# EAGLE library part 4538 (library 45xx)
Dual precision monostable MULTIVIBRATOR
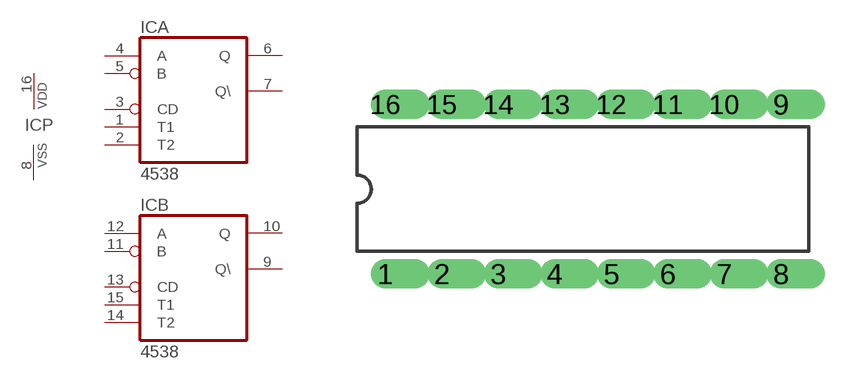
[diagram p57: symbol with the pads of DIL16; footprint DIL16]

Designator prefix IC; gates A=4528 B=4528 P=PWRN

## 4538N  [DIL16]
1  A:T1  in
2  A:T2  in
3  A:CD  in
4  A:A  in
5  A:B  in
6  A:Q  out
7  A:Q\  out
8  P:VSS  pwr
9  B:Q\  out
10  B:Q  out
11  B:B  in
12  B:A  in
13  B:CD  in
14  B:T2  in
15  B:T1  in
16  P:VDD  pwr

## Footprint DIL16 (pad centres in mm)
Dual In Line
drill 0.813 offset: 1 -8.89,-3.81; 2 -6.35,-3.81; 3 -3.81,-3.81; 4 -1.27,-3.81; 5 1.27,-3.81; 6 3.81,-3.81; 7 6.35,-3.81; 8 8.89,-3.81; 9 8.89,3.81; 10 6.35,3.81; 11 3.81,3.81; 12 1.27,3.81; 13 -1.27,3.81; 14 -3.81,3.81; 15 -6.35,3.81; 16 -8.89,3.81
